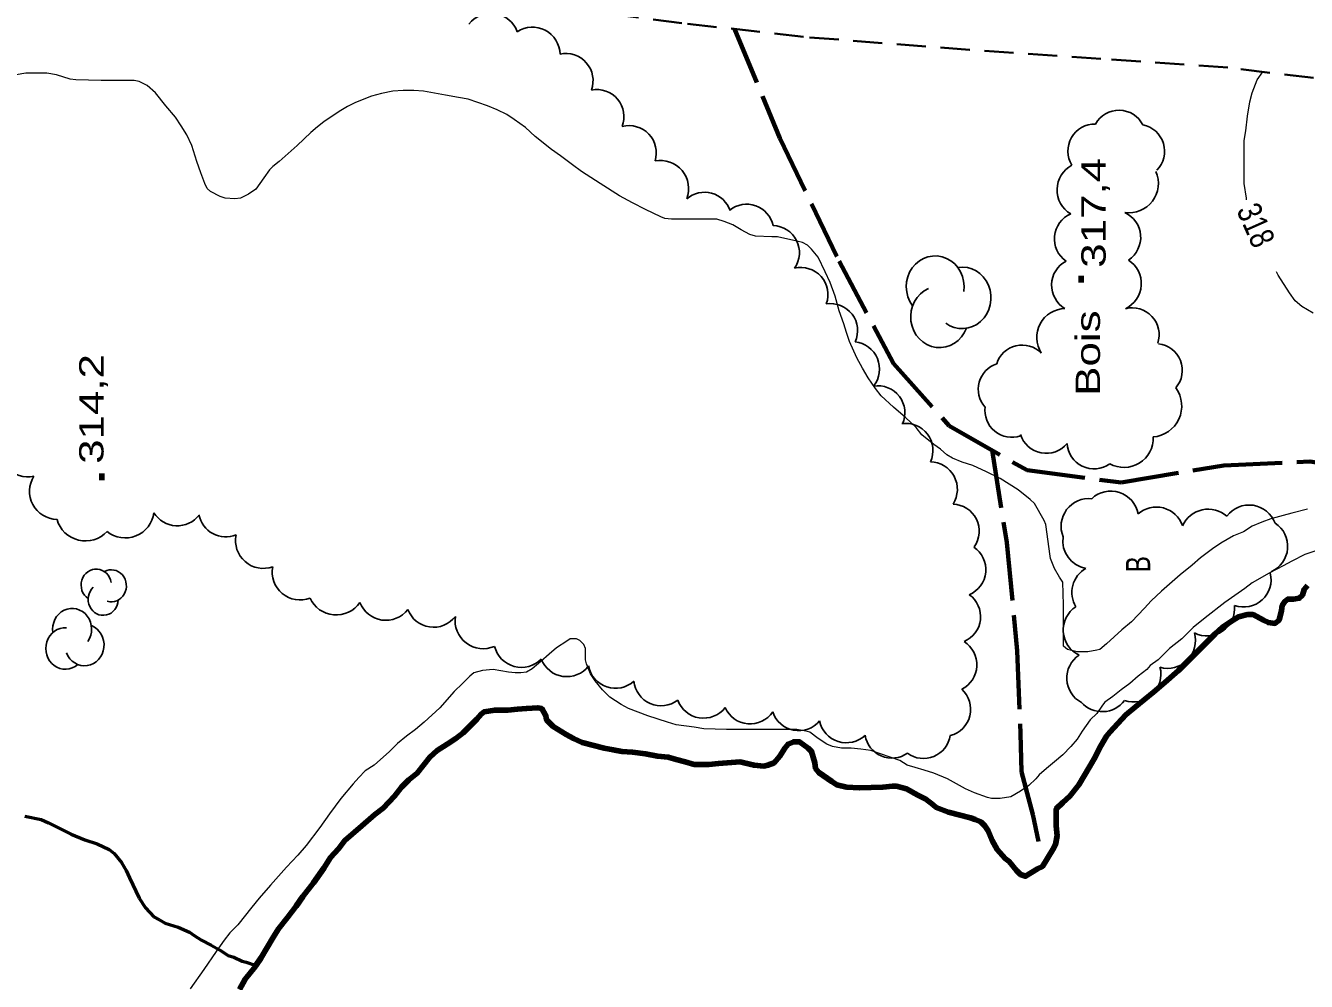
# Model space of a CAD drawing. Extents: x 240591 to 242335, y 5323482 to 5326937.
# Drawn here: x 241811.1 to 241969.2, y 5324675 to 5324793 of the extents above; entities that cross this region are included whole.
import ezdxf

# ---------------------------------------------------------------- set-up
doc = ezdxf.new("R2010")
doc.units = 0
doc.header["$LTSCALE"] = 1.2
for name, pattern in [('DASH_DOUBLE_DOT', [9.2, 5, -1.2, 0.3, -1.2, 0.3, -1.2]), ('LONG_DASHED', [7.5, 6, -1.5]), ('MEDIUM_DASHED', [4.5, 3, -1.5])]:
    doc.linetypes.add(name, pattern=pattern)
for name, color, linetype, lineweight in [('2', 7, 'Continuous', 13), ('21', 7, 'Continuous', 53), ('22', 7, 'LONG_DASHED', 70), ('3', 7, 'Continuous', 140), ('4', 7, 'DASH_DOUBLE_DOT', 53), ('44', 7, 'Continuous', 25)]:
    doc.layers.add(name, color=color, linetype=linetype, lineweight=lineweight)

msp = doc.modelspace()

# ---------------------------------------------------------------- linework, layer by layer
at = {"layer": '2', "linetype": 'LONG_DASHED'}
msp.add_lwpolyline([(241896.4, 5324769.1), (241893.4, 5324769.1), (241890.8, 5324769.1), (241890, 5324769.2), (241889.5, 5324769.4), (241887.6, 5324770.3), (241886, 5324771.1), (241884.4, 5324772), (241882, 5324773.5), (241879.7, 5324775), (241878.6, 5324775.8), (241877.1, 5324776.9), (241876, 5324777.7), (241874, 5324779.3), (241872.8, 5324780.4), (241871.4, 5324781.4), (241870.5, 5324782), (241869.3, 5324782.6), (241868.1, 5324783.1), (241865.7, 5324783.9), (241864.5, 5324784.1), (241862.9, 5324784.4), (241860.2, 5324784.9), (241859, 5324785), (241857.7, 5324785), (241856.4, 5324784.9), (241855, 5324784.6), (241853.8, 5324784.3), (241851.8, 5324783.5), (241850.8, 5324783), (241849.8, 5324782.4), (241847.9, 5324781.1), (241847.1, 5324780.5), (241846.3, 5324779.8), (241844.6, 5324778.2), (241842.4, 5324776.2), (241841.6, 5324775.6), (241841.2, 5324775.2), (241840.5, 5324774.2), (241839.5, 5324772.8), (241838.6, 5324772.2), (241837.6, 5324771.7), (241836.9, 5324771.6), (241835.7, 5324771.7), (241835.1, 5324771.9), (241833.9, 5324772.5), (241833.5, 5324772.9), (241833.2, 5324773.5), (241832.7, 5324774.8), (241832.2, 5324776.2), (241831.6, 5324778.2), (241831, 5324779.5), (241830.3, 5324780.6), (241829.6, 5324781.7), (241828.4, 5324783.1), (241827.1, 5324784.7), (241826.1, 5324785.6), (241825.1, 5324786.1), (241824.5, 5324786.2), (241823.2, 5324786.2), (241820.4, 5324786.2), (241817.3, 5324786.3), (241816.6, 5324786.4), (241814.9, 5324786.9), (241813.7, 5324787.1), (241812.4, 5324787.1), (241811.1, 5324787.1), (241809.9, 5324786.9)], dxfattribs=at)
at = {"layer": '2'}
for points in [[(241961.8, 5324771.5), (241961.8, 5324771.7), (241961.5, 5324773.5), (241961.5, 5324774.8), (241961.5, 5324777.1), (241961.5, 5324778.8), (241961.7, 5324780), (241961.9, 5324781.8), (241962.2, 5324783.6), (241962.5, 5324784.7), (241963.1, 5324786.3), (241963.8, 5324787.3)], [(241943.3, 5324715.9), (241942.2, 5324715.7), (241940.9, 5324715.7), (241939.7, 5324716), (241939.2, 5324716.4), (241939.2, 5324717.1), (241939.2, 5324719), (241939.2, 5324721.5), (241939.1, 5324724.3), (241938.7, 5324724.9), (241938.1, 5324726), (241937.6, 5324727.2), (241937.5, 5324727.8), (241937.3, 5324729.3), (241937, 5324731.4), (241936.8, 5324731.9), (241935.6, 5324734), (241935.1, 5324734.5), (241933.6, 5324735.7), (241932.5, 5324736.4), (241931.4, 5324737.1), (241929.7, 5324737.9), (241928, 5324738.7), (241926.7, 5324739.1), (241925.5, 5324739.6), (241924.8, 5324740), (241924, 5324740.7), (241923.2, 5324741.3), (241921.7, 5324742.5), (241921, 5324743.4), (241919.7, 5324744.6), (241918.2, 5324745.9), (241916.7, 5324747.3), (241916, 5324748.2), (241915.1, 5324749.5), (241914.4, 5324750.7), (241913.7, 5324752), (241912.8, 5324754), (241912.4, 5324755.1), (241912.1, 5324756.2), (241911.5, 5324757.8), (241911, 5324759.6), (241910.4, 5324761.3), (241909.8, 5324762.6), (241908.9, 5324764.4), (241908.1, 5324765.4), (241907.6, 5324765.9), (241907, 5324766.2), (241906.3, 5324766.4), (241903.9, 5324766.9), (241903.2, 5324766.9), (241901.2, 5324767), (241900.5, 5324767.2), (241899.4, 5324767.8), (241898.4, 5324768.4), (241897.3, 5324768.8), (241896.4, 5324769.1)], [(241970, 5324757.5), (241968.6, 5324758.3), (241967.8, 5324759), (241967.1, 5324760), (241965.7, 5324762.2), (241965.5, 5324762.6)], [(241969.3, 5324733.3), (241967.4, 5324732.8), (241964.8, 5324732.1), (241963.7, 5324731.7), (241962.5, 5324731.2), (241961.4, 5324730.5), (241960.2, 5324730), (241958.6, 5324729.1), (241957.6, 5324728.4), (241956.1, 5324727.3), (241955.1, 5324726.4), (241953.6, 5324725.2), (241951.3, 5324723.2), (241950, 5324722), (241949.2, 5324721.1), (241947.6, 5324719.4), (241946.4, 5324718.4), (241944.5, 5324716.7), (241943.7, 5324716), (241943.3, 5324715.9)], [(241970.7, 5324728.3), (241969, 5324727.7), (241967.4, 5324726.9), (241966.3, 5324726.3), (241964.6, 5324725.4), (241962.5, 5324724.2), (241961.6, 5324723.5), (241959.1, 5324721.8), (241956.7, 5324719.9), (241955.2, 5324718.7), (241953.8, 5324717.3), (241952.3, 5324716.1), (241950.9, 5324714.7), (241949.9, 5324714), (241949.5, 5324713.5), (241948.4, 5324712.7), (241947.4, 5324711.8), (241946.3, 5324711), (241945.3, 5324710.2), (241944.3, 5324709.5), (241944, 5324709.1), (241943.3, 5324708.1), (241942.5, 5324707.3), (241941.5, 5324705.9), (241940.9, 5324704.9), (241940.1, 5324704), (241939.1, 5324703), (241938.1, 5324702.1), (241937.1, 5324701.3), (241936.2, 5324700.5), (241935.8, 5324700), (241934.9, 5324699.2), (241933.9, 5324698.5), (241932.7, 5324697.8), (241931.4, 5324697.6), (241930.3, 5324697.6), (241929.8, 5324697.7), (241928.2, 5324698.3)], [(241928.2, 5324698.3), (241927.1, 5324698.8), (241924.9, 5324700), (241923.2, 5324700.7), (241922, 5324701.1), (241920.9, 5324701.4), (241919.9, 5324701.7), (241919, 5324702.3), (241917.8, 5324702.7), (241915.4, 5324703.5), (241914.2, 5324703.7), (241913, 5324703.8), (241911.8, 5324703.8), (241910.7, 5324704), (241910, 5324704.3), (241908.9, 5324705), (241907.9, 5324705.8), (241907.4, 5324705.9), (241906.3, 5324706.1), (241905.7, 5324706.1), (241903.2, 5324706.1), (241900.6, 5324706.1), (241897.6, 5324706.1), (241894.8, 5324706.2), (241893.6, 5324706.4), (241891.4, 5324706.7), (241890.3, 5324707), (241887.9, 5324707.8), (241885.5, 5324708.7), (241884.6, 5324709.2), (241883.2, 5324710.1), (241882.3, 5324711), (241881.4, 5324712.1), (241880.8, 5324713), (241880.3, 5324714.2), (241880.2, 5324714.7), (241880.2, 5324716.1), (241880, 5324716.6), (241879.5, 5324717.1), (241879.1, 5324717.3), (241878.3, 5324717.3), (241877.9, 5324717), (241876.6, 5324716.2), (241875.7, 5324715.4), (241874.7, 5324714.5), (241873.6, 5324713.6), (241872.9, 5324713.2), (241872.2, 5324713.1), (241871.5, 5324713.1), (241870.7, 5324713.2), (241868.8, 5324713.5), (241867.5, 5324713.4), (241866.4, 5324713.1), (241865.9, 5324712.7), (241865, 5324711.8), (241864, 5324710.8), (241862.2, 5324708.8), (241860.3, 5324707), (241859.2, 5324706.1), (241858.1, 5324705.3), (241857, 5324704.4), (241856, 5324703.4), (241854.1, 5324701.7), (241853, 5324701), (241852.2, 5324700.2), (241851.5, 5324699.4), (241850, 5324697.6), (241848.6, 5324695.7), (241847.4, 5324694), (241845.7, 5324691.8), (241844.7, 5324690.6), (241843.3, 5324689.1), (241841.3, 5324686.9), (241839.9, 5324685.3), (241839, 5324684.2), (241837.3, 5324682), (241836.3, 5324681), (241835.6, 5324680.1), (241834.6, 5324678.7), (241833.1, 5324676.5), (241831.4, 5324674.1)]]:
    msp.add_lwpolyline(points, dxfattribs=at)
at = {"layer": '21', "linetype": 'MEDIUM_DASHED', "lineweight": 35}
msp.add_lwpolyline([(241975.4, 5324785.9), (241959.5, 5324787.8), (241943.8, 5324788.9), (241927.6, 5324790), (241907.1, 5324791.6), (241892.1, 5324793.3), (241872.3, 5324795.8), (241852.8, 5324797.9), (241834.4, 5324799.1), (241816.1, 5324801), (241799.1, 5324803)], dxfattribs=at)
at = {"layer": '22'}
for points in [[(241898.6, 5324792.6), (241904.2, 5324779.1), (241911.5, 5324763.9), (241918.2, 5324751.3), (241925.1, 5324743.6), (241934.7, 5324738.1), (241946.3, 5324736.6), (241959, 5324738.7), (241969.6, 5324739.2), (241983.4, 5324737.1), (241993.5, 5324736.8), (242002.3, 5324737.3)], [(241930.4, 5324740.6), (241932.2, 5324729.2), (241933.5, 5324715.8), (241933.9, 5324705.6), (241934, 5324700.9), (241935.4, 5324695.6), (241936.1, 5324692.3)]]:
    msp.add_lwpolyline(points, dxfattribs=at)
at = {"layer": '3'}
for p, q in [((241941.4, 5324761.3), (241941.4, 5324762.1)), ((241820.5, 5324736.9), (241820.5, 5324737.7))]:
    msp.add_line(p, q, dxfattribs=at)
at = {"layer": '4', "linetype": 'Continuous', "lineweight": 90}
for points in [[(241969.3, 5324723.9), (241968.9, 5324723.4), (241968.7, 5324722.7), (241968.3, 5324722.3), (241967.6, 5324722.2), (241966.9, 5324722.2), (241966.5, 5324721.9), (241966.2, 5324721.4), (241966.1, 5324720.8), (241965.8, 5324719.6), (241965.3, 5324719.2), (241964.5, 5324719.3), (241963.9, 5324719.6), (241962.6, 5324720.3), (241961.9, 5324720.3), (241960.8, 5324720), (241959.8, 5324719.4), (241958.8, 5324718.7), (241957.9, 5324717.9), (241957, 5324717), (241955.4, 5324715.4), (241953.4, 5324713.4), (241951.7, 5324711.9), (241950.3, 5324710.7), (241948.1, 5324708.9), (241946.9, 5324707.9), (241944.9, 5324705.8), (241944.5, 5324705.3), (241943.8, 5324704.1), (241943, 5324702.5), (241942.4, 5324701.5), (241941.1, 5324699.3), (241940, 5324697.9), (241939.1, 5324697.1), (241938.3, 5324696.3), (241938.3, 5324695.7), (241938.3, 5324694.2), (241938.4, 5324693), (241938.2, 5324691.9), (241937.9, 5324691.3), (241936.6, 5324689.2), (241936, 5324688.9), (241934.5, 5324688), (241933.9, 5324688.2), (241933.4, 5324688.7), (241932.5, 5324689.8), (241932, 5324690.2), (241931, 5324691.3), (241930.4, 5324692.4), (241929.9, 5324693.6), (241929.5, 5324694.2), (241929, 5324694.7), (241928.3, 5324695), (241927.7, 5324695.2), (241925, 5324695.9), (241923.5, 5324696.5), (241923.1, 5324696.8), (241922.2, 5324697.5), (241921.2, 5324698)], [(241921.2, 5324698), (241919.8, 5324698.8), (241918.6, 5324699.1), (241918.1, 5324699.1), (241916.9, 5324699), (241914, 5324698.9), (241912.4, 5324699), (241911.2, 5324699.3), (241910.6, 5324699.7), (241909, 5324700.8), (241908.6, 5324701.3), (241908.5, 5324702), (241908.1, 5324703.4), (241907.7, 5324703.8), (241906.6, 5324704.6), (241905.9, 5324704.6), (241905.2, 5324704.3), (241904.8, 5324703.8), (241904.2, 5324702.8), (241903.5, 5324702), (241902.7, 5324701.7), (241902.2, 5324701.6), (241901, 5324701.7), (241899.8, 5324702), (241899.3, 5324702.1), (241897.7, 5324702), (241896.6, 5324701.9), (241895.4, 5324701.8), (241893.6, 5324701.8), (241892.5, 5324702.1), (241891.4, 5324702.4), (241890.4, 5324702.7), (241889.1, 5324702.8), (241887.6, 5324703.1), (241886, 5324703.3), (241884.7, 5324703.4), (241883.6, 5324703.6), (241882.5, 5324703.8), (241879.8, 5324704.5), (241878.7, 5324705), (241877.8, 5324705.5), (241876.2, 5324706.5), (241875.4, 5324707.3), (241875.3, 5324707.8), (241874.8, 5324708.7), (241874.3, 5324708.8), (241872.9, 5324708.7), (241871.8, 5324708.6), (241870.6, 5324708.5), (241869, 5324708.5), (241867.7, 5324708.3), (241867.3, 5324708), (241866.8, 5324707.4), (241865.1, 5324705.7), (241864.2, 5324705), (241863.1, 5324704.3), (241861.9, 5324703.5), (241861, 5324702.7), (241860.2, 5324701.7), (241859.4, 5324700.7), (241858.4, 5324699.9), (241857.5, 5324699), (241856.6, 5324697.9), (241855.2, 5324696.4), (241854.2, 5324695.6), (241852.6, 5324694.2), (241850.5, 5324692.4), (241849.7, 5324691.4), (241848.7, 5324690.3), (241847.9, 5324689), (241846.6, 5324687.2), (241845.3, 5324685.5), (241844.5, 5324684.3), (241843.4, 5324682.9), (241842.3, 5324681.5), (241841.7, 5324680.5), (241840.1, 5324677.9), (241839.5, 5324677)], [(241839.5, 5324677), (241839.4, 5324676.8), (241838.2, 5324675.3), (241837.5, 5324674)]]:
    msp.add_lwpolyline(points, dxfattribs=at)
at = {"layer": '4'}
msp.add_lwpolyline([(241811, 5324695.4), (241813, 5324695), (241813.9, 5324694.6), (241816.7, 5324693.2), (241818.4, 5324692.5), (241819.9, 5324692), (241821.4, 5324691.3), (241822, 5324690.8), (241822.9, 5324689.7), (241823.5, 5324688.7), (241823.9, 5324687.8), (241825.1, 5324685.3), (241825.9, 5324684.1), (241826.9, 5324683), (241827.6, 5324682.6), (241828.3, 5324682.2), (241829.9, 5324681.7), (241831.3, 5324681.1), (241831.9, 5324680.7), (241832.8, 5324680.1), (241834, 5324679.5), (241835, 5324678.9), (241836.1, 5324678.2), (241836.8, 5324678), (241837.8, 5324677.5), (241838.3, 5324677.4), (241839.5, 5324677)], dxfattribs=at)
at = {"layer": '44'}
for centre, radius, start, end in [((241873.64, 5324789.387), 3.412, 1.56952, 123.23589), ((241941.841, 5324772.713), 3.442, 117.71354, 239.42702), ((241815.017, 5324735.509), 3.46, 147.46375, 269.06067), ((241900.525, 5324710.165), 3.369, 203.72145, 325.76649), ((241906.506, 5324709.328), 3.366, 198.31277, 320.13686)]:
    msp.add_arc(centre, radius, start, end, dxfattribs=at)
for centre, major_axis, ratio, start_param, end_param in [((241868.528, 5324791.048), (1.17, 3.25), 0.999885, 5.4100485, 7.5344388), ((241877.759, 5324786.185), (-3.303, -0.675), 0.999983, 2.5935128, 4.7227398), ((241881.573, 5324781.728), (2.575, 2.185), 0.998705, 5.2191115, 7.3425575), ((241946.048, 5324779.22), (-3.32, 0.057), 0.999935, 3.6342274, 5.7905507), ((241885.568, 5324777.274), (2.443, 2.326), 0.999631, 5.2231223, 7.3443507), ((241943.068, 5324777.513), (-1.654, -2.888), 0.999194, 3.6375699, 5.7872079), ((241948.343, 5324777.475), (-0.974, 3.186), 0.999196, 3.6372781, 5.7874998), ((241889.441, 5324772.856), (2.856, 1.999), 0.999509, 5.3096606, 7.431529), ((241947.276, 5324773.509), (2.302, -2.813), 0.999936, 5.4576523, 7.5824435), ((241894.877, 5324769.09), (-2.016, 2.661), 0.999477, 4.3871779, 6.3454533), ((241900.086, 5324767.606), (-2.544, -2.164), 0.999249, 2.6489223, 4.6847642), ((241941.426, 5324766.676), (-3.337, 0.321), 0.99979, 5.2183568, 7.3449231), ((241945.361, 5324766.852), (3.37, 0.044), 0.999093, 5.2872083, 7.4093505), ((241903.258, 5324764.966), (-2.489, 2.235), 0.999826, 3.2631623, 5.4163643), ((241923.363, 5324760.773), (-0.001, 3.796), 0.939648, 4.5528225, 8.5226976), ((241906.779, 5324759.797), (0.351, 3.327), 0.999485, 4.4676039, 6.6236713), ((241926.684, 5324759.389), (-0.001, 3.796), 0.939648, 2.539894, 6.4264693), ((241941.077, 5324760.956), (-3.347, 0.088), 0.999994, 5.2222227, 7.3486066), ((241945.315, 5324761.161), (3.486, -0.178), 0.99038, 5.2149379, 7.3237786), ((241923.905, 5324757.042), (-0.001, 3.796), 0.939648, 0.3962545, 4.3352635), ((241910.436, 5324755.346), (-3.086, 1.29), 0.999719, 3.1100952, 5.2631771), ((241939.466, 5324754.502), (-3.118, 1.756), 0.996385, 5.2477232, 7.366598), ((241947.684, 5324754.845), (3.169, 0.995), 0.997804, 5.6497575, 7.8071312), ((241913.092, 5324750.592), (3.124, 1.328), 0.998353, 5.2157834, 7.3380088), ((241934.109, 5324750.248), (-2.995, -1.414), 0.999731, 3.4819185, 5.5348125), ((241950.543, 5324750.436), (1.678, 2.863), 0.998633, 4.5344932, 6.6940737), ((241932.014, 5324748.11), (-3.281, -0.574), 0.995487, 4.8646758, 6.8269807), ((241916.274, 5324745.203), (3.076, 1.314), 0.997422, 5.4518763, 7.6056933), ((241949.969, 5324746.031), (2.77, -2.634), 0.999969, 5.5486463, 7.6722786), ((241932.817, 5324745.493), (2.44, -2.258), 0.999739, 3.7509433, 5.7909528), ((241919.729, 5324740.55), (-2.847, 1.76), 0.999826, 3.2636701, 5.4157507), ((241937.058, 5324743.513), (2.787, 1.8), 0.999923, 2.8710773, 5.0307754), ((241946.661, 5324742.058), (1.771, -3.144), 0.99788, 5.2616806, 7.3867906), ((241811.337, 5324740.68), (3.366, 0.487), 0.998771, 2.6335518, 4.7952318), ((241942.957, 5324741.597), (-1.202, -3.103), 0.997532, 5.1313269, 7.2824129), ((241922.713, 5324735.764), (-2.89, 1.765), 0.999994, 3.1176723, 5.2440344), ((241945.038, 5324732.13), (-3.158, 1.306), 0.996043, 3.7091714, 5.8652496), ((241942.317, 5324731.2), (-1.936, -2.822), 0.996488, 3.6380345, 5.7027691), ((241823.383, 5324733.308), (0.891, -3.442), 0.999778, 5.3471633, 7.4772339), ((241829.797, 5324734.661), (1.816, -2.881), 0.997531, 4.7051653, 6.635935), ((241835.81, 5324733.282), (2.605, -2.192), 0.999612, 4.0438022, 5.7911639), ((241925.455, 5324730.592), (-2.034, 2.648), 0.999847, 3.4375782, 5.5967901), ((241950.659, 5324730.161), (-3.201, 1.194), 0.996045, 3.832106, 5.790967), ((241957.067, 5324729.799), (-1.017, 3.357), 0.998546, 5.2713189, 7.1308182), ((241962.115, 5324730.419), (-3.377, 0.488), 0.996028, 3.6343201, 5.7904578), ((241818.466, 5324733.014), (-0.854, -3.534), 0.999995, 5.2178961, 7.3466612), ((241963.452, 5324728.716), (-0.56, 3.374), 0.999792, 3.3906128, 5.540463), ((241840.427, 5324729.425), (-2.369, -2.485), 0.99829, 5.2689756, 7.3914232), ((241942.529, 5324729.353), (3.155, -1.306), 0.997353, 3.3769233, 4.9374495), ((241926.266, 5324725.833), (0.312, 3.333), 0.999984, 3.6352733, 5.7895047), ((241844.963, 5324725.54), (-2.662, -2.174), 0.999884, 5.4048943, 7.5342813), ((241819.8, 5324723.927), (-0.001, 1.982), 0.939648, 4.8832488, 8.8531238), ((241821.661, 5324723.842), (-0.001, 1.982), 0.939648, 2.8703203, 6.7568956), ((241943.644, 5324723.037), (-1.73, -2.944), 0.997771, 4.1904262, 5.790389), ((241961.407, 5324724.602), (3.087, -1.464), 0.985974, 4.8189509, 6.973158), ((241820.662, 5324722.182), (-0.001, 1.982), 0.939648, 0.7266808, 4.6656898), ((241849.413, 5324723.783), (-0.838, -3.435), 0.999837, 5.3750785, 7.4979613), ((241855.548, 5324723.018), (-0.497, -3.398), 0.99875, 5.2198943, 7.3453424), ((241925.631, 5324720.036), (3.297, -0.53), 0.998396, 5.2680872, 7.393581), ((241956.903, 5324721.056), (3.343, -0.71), 0.99491, 4.4486929, 6.6006761), ((241816.826, 5324718.492), (0.001, -2.562), 0.939648, 0.9383664, 4.8773754), ((241861.441, 5324722.121), (-0.935, -3.257), 0.999755, 5.3509312, 7.4794813), ((241867.579, 5324719.565), (-2.372, -2.554), 0.999606, 5.3179871, 7.4422194), ((241942.623, 5324718.386), (-3.457, -0.187), 0.992233, 5.2373238, 7.3511182), ((241815.987, 5324716.105), (0.001, -2.562), 0.939648, 3.0820059, 6.9685812), ((241818.361, 5324716.535), (0.001, -2.562), 0.939648, 5.0949344, 9.0648094), ((241925.138, 5324714.093), (3.372, -0.166), 0.999908, 5.2225294, 7.347023), ((241952.055, 5324717.085), (2.222, -2.612), 0.999383, 5.2987473, 7.4286984), ((241872.288, 5324717.193), (-0.884, -3.304), 0.999441, 5.2167775, 7.3445288), ((241943.01, 5324712.453), (0.323, -3.394), 0.99986, 3.634237, 5.6999789), ((241877.895, 5324716.009), (2.081, 2.658), 0.999983, 2.5981606, 4.7206476), ((241883.891, 5324714.576), (-1.549, -3.004), 0.999822, 5.3747109, 7.4993449), ((241947.819, 5324712.911), (2.493, 2.323), 0.998138, 3.6315855, 5.7931924), ((241889.529, 5324712.41), (-1.558, -2.996), 0.999237, 5.2894287, 7.4160654), ((241924.397, 5324708.602), (3.24, -0.817), 0.997573, 5.2076417, 7.3643983), ((241894.768, 5324710.91), (-0.528, -3.36), 0.999041, 5.222349, 7.3439829), ((241943.956, 5324711.717), (3.388, -0.478), 0.996496, 4.010887, 5.7874047), ((241912.397, 5324707.849), (-1.015, -3.22), 0.999994, 5.2202621, 7.3432457), ((241918.008, 5324705.918), (3.156, -1.096), 0.999596, 3.6346878, 5.6615291), ((241921.907, 5324705.88), (2.227, -2.509), 0.998498, 4.9246509, 6.975899)]:
    msp.add_ellipse(centre, major_axis=major_axis, ratio=ratio, start_param=start_param, end_param=end_param, dxfattribs=at)

# ---------------------------------------------------------------- texts
at = {"layer": '2', "width": 0.8}
msp.add_text('318', height=3, rotation=293.942, dxfattribs=at).set_placement((241960.5, 5324770.2))
at = {"layer": '3', "width": 1.35}
for s, p in [('317,4', (241944.4, 5324763.1)), ('314,2', (241820.7, 5324738.9))]:
    msp.add_text(s, height=3, rotation=90, dxfattribs=at).set_placement(p)
at = {"layer": '44'}
for s, width, p in [('Bois', 1.35, (241943.7, 5324747.3)), ('B', 0.75, (241949.9, 5324725.5))]:
    msp.add_text(s, height=3, rotation=90, dxfattribs=dict(at, width=width)).set_placement(p)

doc.saveas('drawing.dxf')
